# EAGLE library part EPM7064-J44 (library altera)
EPM7064 MAX 7000 family
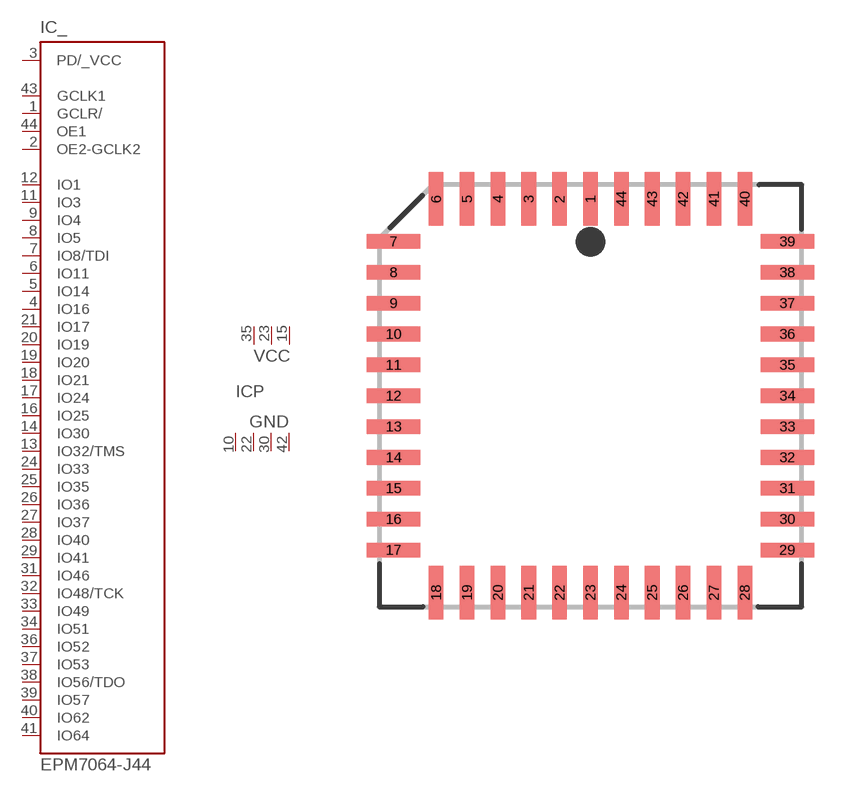
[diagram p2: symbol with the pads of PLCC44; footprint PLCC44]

Designator prefix IC; gates _=7064-44 P=PWR3-4

## EPM7064-J44  [PLCC44]
1  _:GCLR/  in
2  _:OE2-GCLK2  in
3  _:PD/_VCC  pas
4  _:IO16
5  _:IO14
6  _:IO11
7  _:IO8/TDI
8  _:IO5
9  _:IO4
10  P:GND  pwr
11  _:IO3
12  _:IO1
13  _:IO32/TMS
14  _:IO30
15  P:VCC  pwr
16  _:IO25
17  _:IO24
18  _:IO21
19  _:IO20
20  _:IO19
21  _:IO17
22  P:GND  pwr
23  P:VCC  pwr
24  _:IO33
25  _:IO35
26  _:IO36
27  _:IO37
28  _:IO40
29  _:IO41
30  P:GND  pwr
31  _:IO46
32  _:IO48/TCK
33  _:IO49
34  _:IO51
35  P:VCC  pwr
36  _:IO52
37  _:IO53
38  _:IO56/TDO
39  _:IO57
40  _:IO62
41  _:IO64
42  P:GND  pwr
43  _:GCLK1  in
44  _:OE1  in

## Footprint PLCC44 (pad centres in mm)
Plastic J-Lead Chip Carrier
smd 0.6 x 2.2: 1 0,8.1; 2 -1.27,8.1; 3 -2.54,8.1; 4 -3.81,8.1; 5 -5.08,8.1; 6 -6.35,8.1; 18 -6.35,-8.1; 19 -5.08,-8.1; 20 -3.81,-8.1; 21 -2.54,-8.1; 22 -1.27,-8.1; 23 0,-8.1; 24 1.27,-8.1; 25 2.54,-8.1; 26 3.81,-8.1; 27 5.08,-8.1; 28 6.35,-8.1; 40 6.35,8.1; 41 5.08,8.1; 42 3.81,8.1; 43 2.54,8.1; 44 1.27,8.1
smd 2.2 x 0.6: 7 -8.1,6.35; 8 -8.1,5.08; 9 -8.1,3.81; 10 -8.1,2.54; 11 -8.1,1.27; 12 -8.1,0; 13 -8.1,-1.27; 14 -8.1,-2.54; 15 -8.1,-3.81; 16 -8.1,-5.08; 17 -8.1,-6.35; 29 8.1,-6.35; 30 8.1,-5.08; 31 8.1,-3.81; 32 8.1,-2.54; 33 8.1,-1.27; 34 8.1,0; 35 8.1,1.27; 36 8.1,2.54; 37 8.1,3.81; 38 8.1,5.08; 39 8.1,6.35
